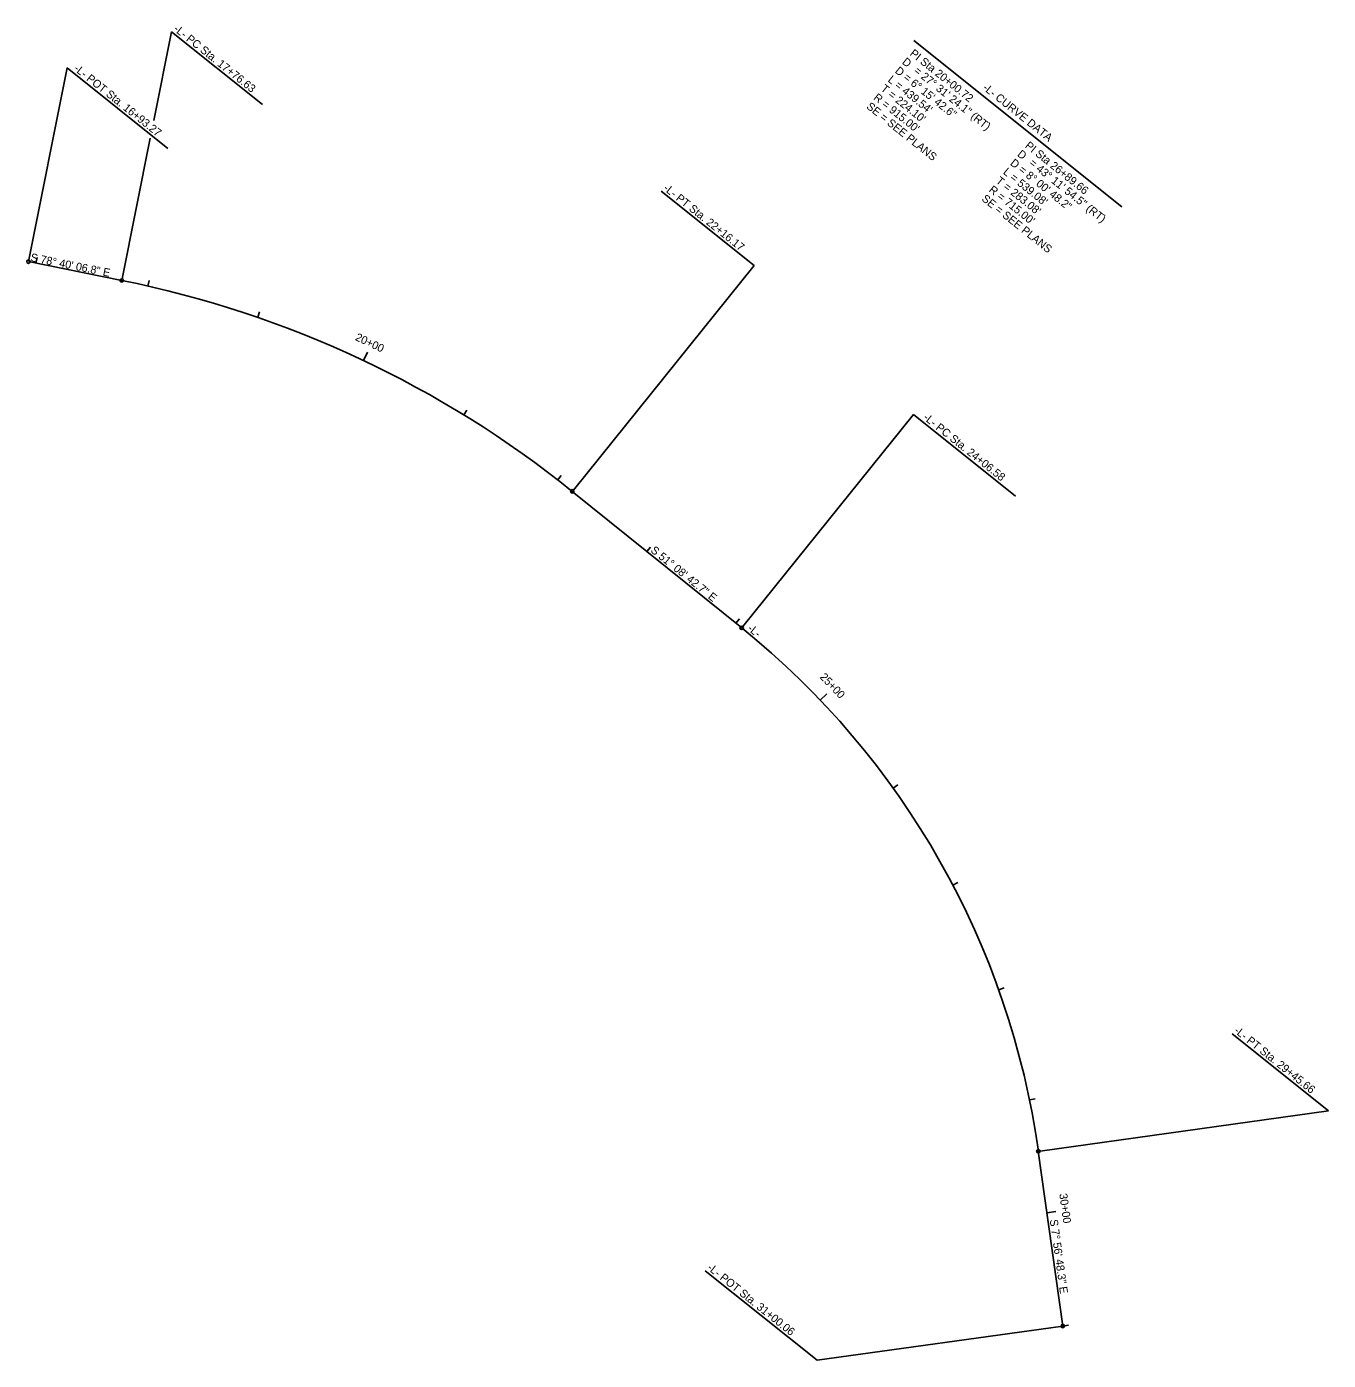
# Model space of a CAD drawing. Extents: x 1734329 to 1735468, y 914899 to 916066.
import ezdxf

# ---------------------------------------------------------------- set-up
doc = ezdxf.new("R2010")
doc.units = 0
for name, color, linetype in [('Prop Easement Construction', 7, 'Continuous'), ('Prop Easement Construction Station Offsets', 7, 'Continuous'), ('Prop Parcel Number CELL', 7, 'Continuous'), ('Prop Parcel Number Text', 7, 'Continuous'), ('Prop ROW Station Offsets', 7, 'Continuous'), ('Prop SS Cut Line', 7, 'Continuous'), ('Prop SS Transition Line', 7, 'Continuous')]:
    doc.layers.add(name, color=color, linetype=linetype)

msp = doc.modelspace()

# ---------------------------------------------------------------- linework, layer by layer
at = {"layer": 'Prop Easement Construction Station Offsets'}
for p, q in [((1734336.7, 915858.8), (1734337.7, 915863.7)), ((1734434.7, 915838.8), (1734435.8, 915843.7)), ((1734530.8, 915811.4), (1734532.4, 915816.1)), ((1734711.2, 915726), (1734713.8, 915730.3)), ((1734793.4, 915669.1), (1734796.4, 915673.1)), ((1734871.3, 915606.5), (1734874.5, 915610.4)), ((1734949.2, 915543.8), (1734952.3, 915547.7)), ((1735086.8, 915399.5), (1735090.9, 915402.4)), ((1735139.2, 915314.5), (1735143.6, 915316.8)), ((1735179.3, 915222.9), (1735184, 915224.6)), ((1735206.2, 915126.7), (1735211.1, 915127.7)), ((1735235.2, 914928.8), (1735240.2, 914929.5))]:
    msp.add_line(p, q, dxfattribs=at)
at = {"layer": 'Prop Parcel Number CELL'}
for p, q in [((1734439.8, 915983.5), (1734455.4, 916061.1)), ((1734534.9, 915997.5), (1734455.4, 916061.1)), ((1734330.4, 915861.6), (1734364, 916029.6)), ((1734452.1, 915959.1), (1734364, 916029.6)), ((1734412.1, 915845.2), (1734436.7, 915968.2)), ((1734883.9, 915921.7), (1734965.2, 915856.7)), ((1734807, 915660.3), (1734965.2, 915856.7)), ((1734955.3, 915540.8), (1735104.8, 915726.4)), ((1735194, 915655), (1735104.8, 915726.4)), ((1735467.7, 915117.1), (1735383.4, 915184.6)), ((1735215.4, 915081.9), (1735467.7, 915117.1)), ((1734922.4, 914977.2), (1735020.4, 914898.8)), ((1735020.4, 914898.8), (1735235.3, 914928.8))]:
    msp.add_line(p, q, dxfattribs=at)
for centre in [(1734330.1, 915860.1), (1734411.8, 915843.7), (1734806, 915659.1), (1734954.3, 915539.6), (1735213.9, 915081.7), (1735235.3, 914928.8)]:
    msp.add_circle(centre, 1.5, dxfattribs=at)
at = {"layer": 'Prop Parcel Number Text'}
msp.add_line((1735105, 916053.7), (1735287, 915908.1), dxfattribs=at)
at = {"layer": 'Prop ROW Station Offsets'}
for p, q in [((1734330.1, 915860.1), (1734411.8, 915843.7)), ((1734806, 915659.1), (1734954.3, 915539.6)), ((1735213.9, 915081.7), (1735235.3, 914928.8))]:
    msp.add_line(p, q, dxfattribs=at)
for centre, radius, start, end in [((1734232, 914946.5), 915, 51.1452, 78.6686), ((1734505.8, 914982.8), 715, 7.9467, 51.1452)]:
    msp.add_arc(centre, radius, start, end, dxfattribs=at)
at = {"layer": 'Prop SS Transition Line'}
for p, q in [((1734623.3, 915773.7), (1734626.7, 915780.9)), ((1735023, 915476.5), (1735028.8, 915482)), ((1735221.4, 915027.9), (1735229.3, 915029))]:
    msp.add_line(p, q, dxfattribs=at)

# ---------------------------------------------------------------- texts
at = {"layer": 'Prop Easement Construction'}
for s, rotation, p in [('20+00', 334.6813, (1734615.5, 915791.7)), ('25+00', 313.6592, (1735022.2, 915496.2)), ('30+00', 277.9467, (1735232.2, 915044.3))]:
    msp.add_text(s, height=7, rotation=rotation, dxfattribs=at).set_placement(p)
at = {"layer": 'Prop Parcel Number CELL'}
for s, p in [('-L- PC Sta. 17+76.63', (1734456.6, 916062.7)), ('-L- POT Sta. 16+93.27', (1734369.3, 916028)), ('-L- PT Sta. 22+16.17', (1734885.2, 915923.3)), ('-L- PC Sta. 24+06.58', (1735112.6, 915722.7)), ('-L- PT Sta. 29+45.66', (1735384.6, 915186.2)), ('-L- POT Sta. 31+00.06', (1734923.6, 914978.8))]:
    msp.add_text(s, height=7, rotation=321.3297, dxfattribs=at).set_placement(p)
at = {"layer": 'Prop Parcel Number Text'}
for s, p in [('PI Sta 20+00.72', (1735100.9, 916041.2)), ('D = 6%%d 15\' 42.6"', (1735087.9, 916026)), ('D', (1735094.1, 916033.8)), ("L = 439.54'", (1735081.6, 916018.2)), ('= 27%%d 31\' 24.1" (RT)', (1735104.3, 916026)), ("R = 915.00'", (1735069.1, 916002.6)), ("T = 224.10'", (1735075.4, 916010.4)), ('-L- CURVE DATA', (1735164.7, 916011.2)), ('SE = SEE PLANS', (1735062.9, 915994.8)), ('PI Sta 26+89.66', (1735201.7, 915960.5)), ('D = 8%%d 00\' 48.2"', (1735188.7, 915945.3)), ('D', (1735194.9, 915953.1)), ('= 43%%d 11\' 54.5" (RT)', (1735205.2, 915945.3)), ("L = 539.08'", (1735182.5, 915937.5)), ("R = 715.00'", (1735170, 915921.9)), ("T = 283.08'", (1735176.2, 915929.7)), ('SE = SEE PLANS', (1735163.7, 915914.1))]:
    msp.add_text(s, height=7, rotation=321.3297, dxfattribs=at).set_placement(p)
at = {"layer": 'Prop SS Cut Line'}
for s, rotation, p in [('S 78%%d 40\' 06.8" E', 348.6686, (1734331.5, 915860.7)), ('S 51%%d 08\' 42.7" E', 321.1452, (1734874, 915606.5)), ('-L-', 321.1452, (1734958.8, 915538.1)), ('S 7%%d 56\' 48.3" E', 277.9467, (1735223.9, 915021.7))]:
    msp.add_text(s, height=7, rotation=rotation, dxfattribs=at).set_placement(p)

doc.saveas('drawing.dxf')
